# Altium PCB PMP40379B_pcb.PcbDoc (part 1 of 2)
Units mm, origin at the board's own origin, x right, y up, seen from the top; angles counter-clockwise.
Board outline 160 x 130 mm, 2 copper layers (Top Layer, Bottom Layer), stack 1.575 mm thick; 126 components, 53 nets, 295 pads, 84 vias.
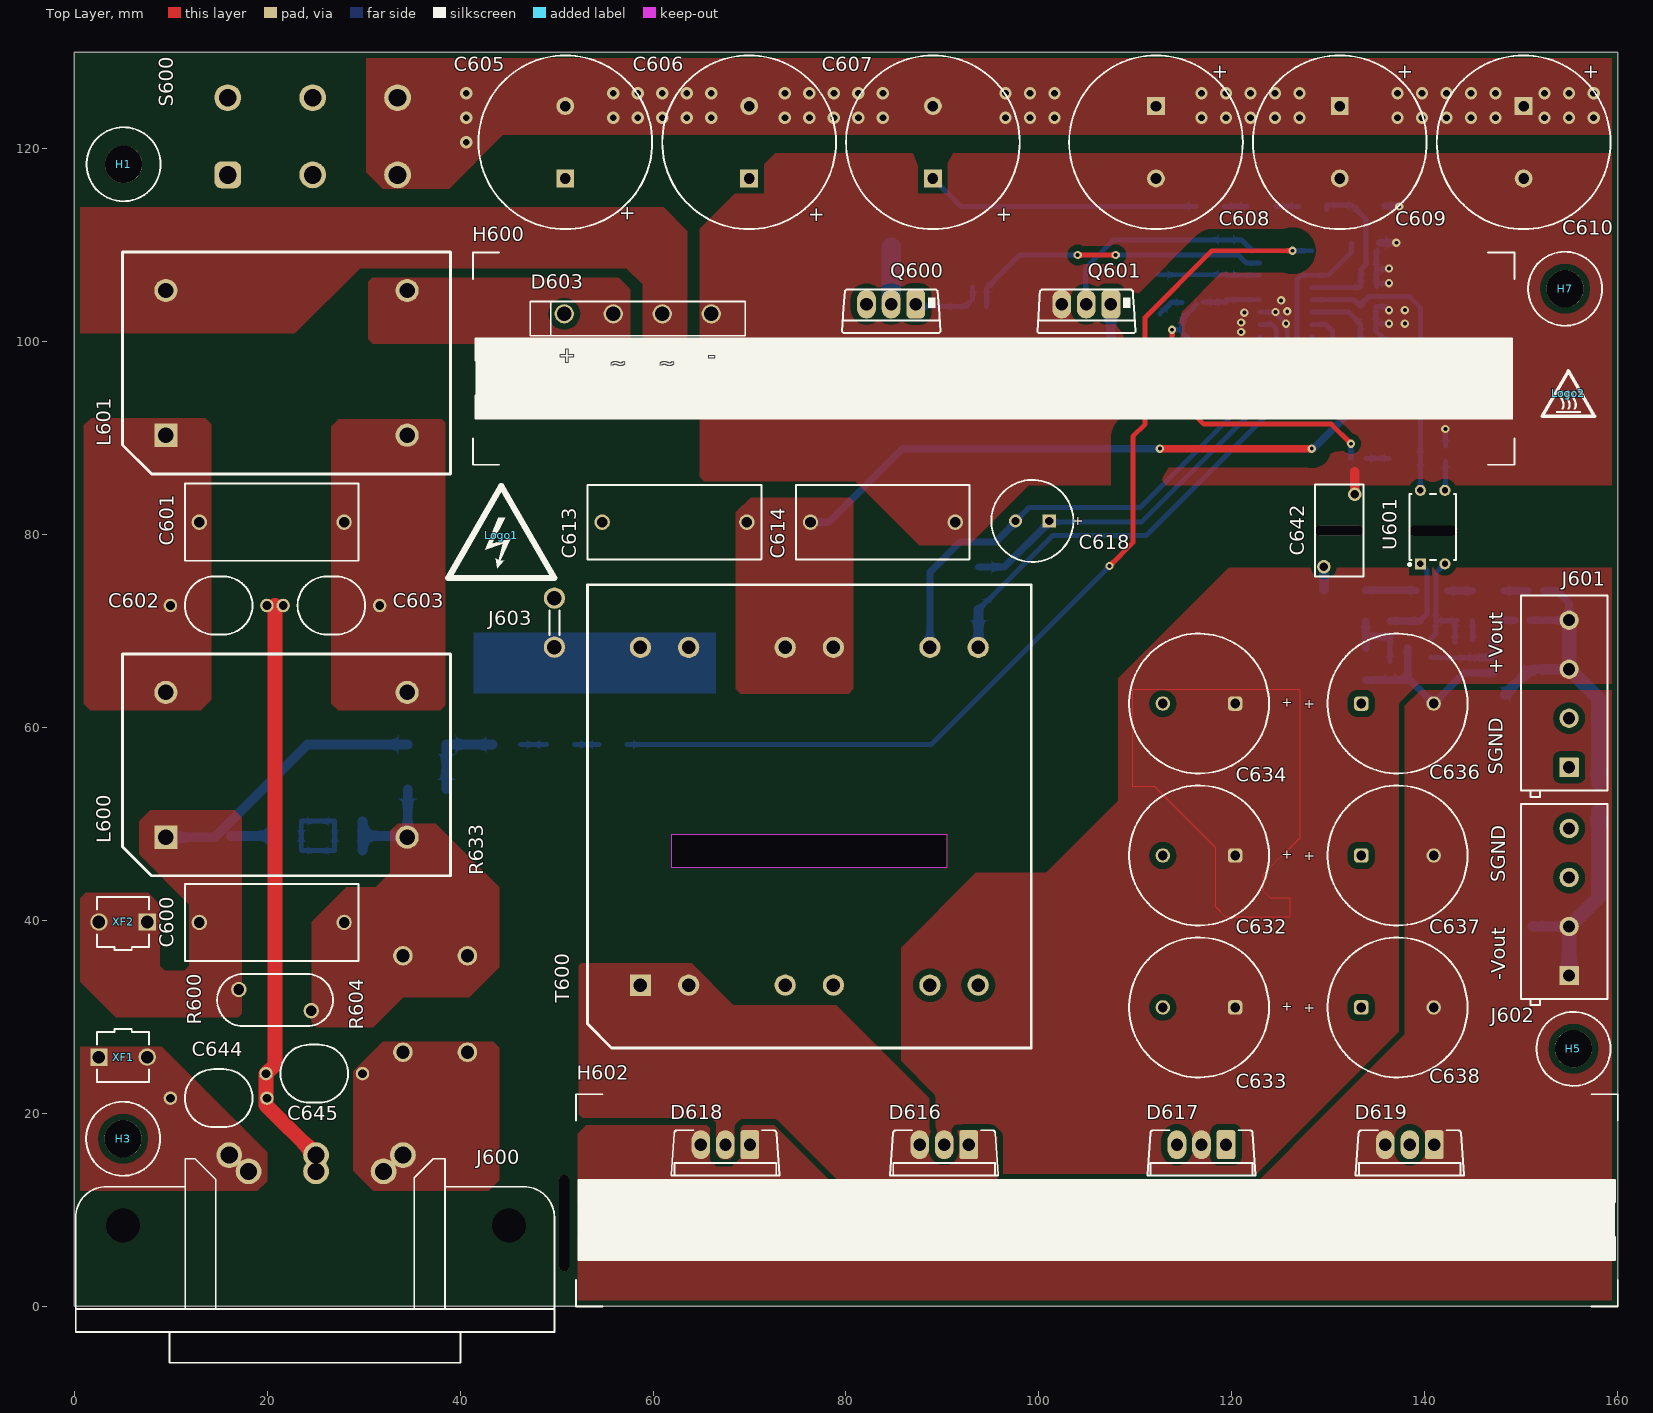
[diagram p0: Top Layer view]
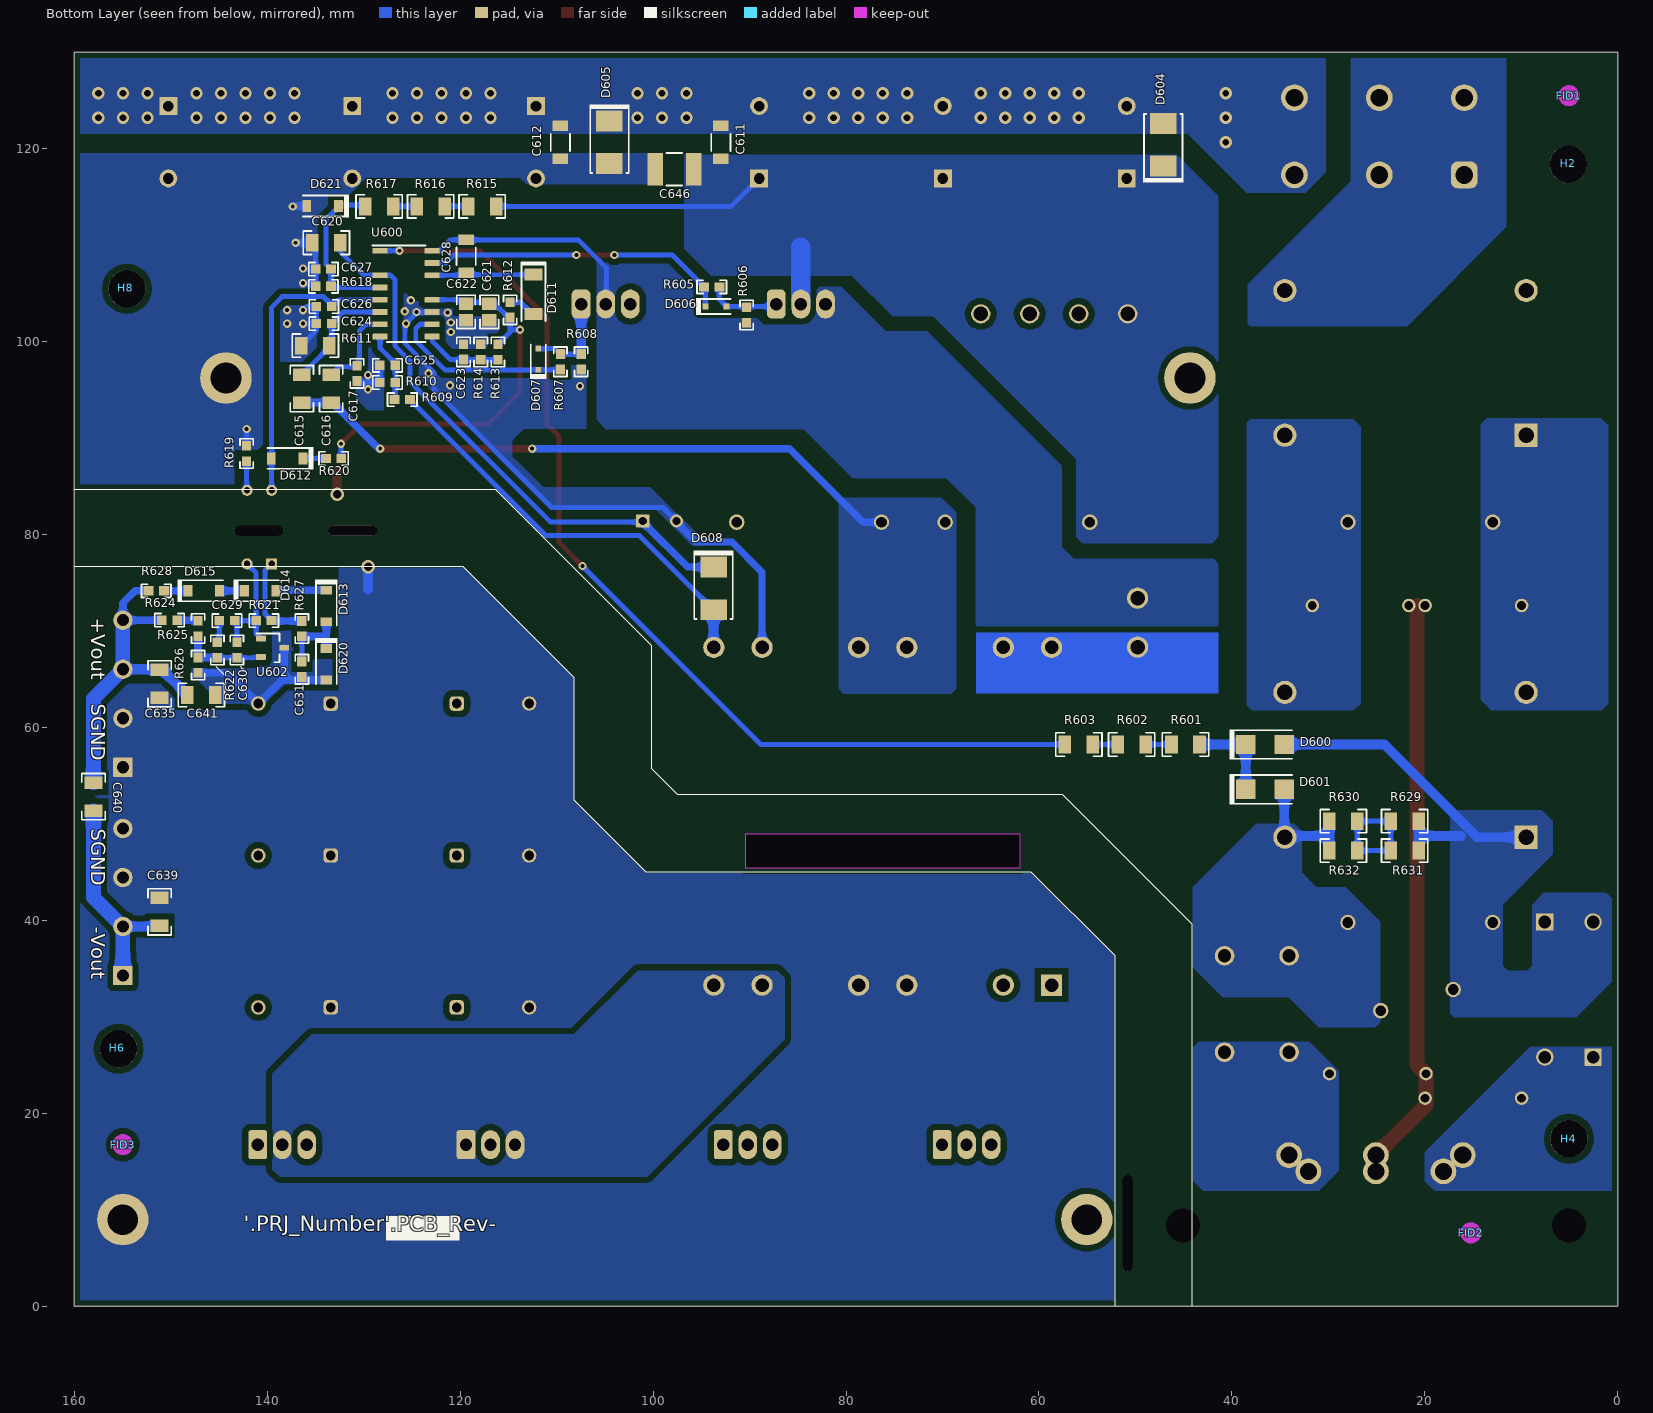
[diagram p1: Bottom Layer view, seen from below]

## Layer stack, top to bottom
Top Solder: solder mask 0.0102, Solder Resist, Dk 3.5
Top Layer: signal copper 0.0356
Dielectric1: core 1.5037, FR-4, Dk 4.8
Bottom Layer: signal copper 0.0356
Bottom Solder: solder mask 0.0102, Solder Resist, Dk 3.5

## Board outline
0,0 0,130 160,130 160,0
cut-out: 61.95,48.95 90.45,48.95 90.45,45.45 61.95,45.45

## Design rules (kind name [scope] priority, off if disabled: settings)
AcuteAngle [All] p1: minimum=4.50000000000000E+0001 checktracksonly=FALSE
AssemblyTestPointUsage [All] p1: valid=2
BoardOutlineClearance BoardOutlineClearance_MountingHoles [OnCopper and InComponentClass('Mounting Holes')] p1: gap=1.016 ignorepadtopadclearanceinfootprint=FALSE
BoardOutlineClearance BoardOutlineClearance_Poly [OnCopper and IsPoly] p2: gap=0.635 ignorepadtopadclearanceinfootprint=FALSE
BoardOutlineClearance [OnCopper and Not InComponentClass('Logo') and not InComponentClass('FiducialMark') and not InRegion(1000,500,4000,800) and not InPoly] p3: gap=1.905 ignorepadtopadclearanceinfootprint=FALSE
Clearance "Schematic Clearance Constraint_2" [InNet('NetC628_1')] p1: gap=2.5 ignorepadtopadclearanceinfootprint=FALSE
Clearance "Schematic Clearance Constraint" [InNet('NetR603_1')] p2: gap=2 ignorepadtopadclearanceinfootprint=FALSE
Clearance "Schematic Clearance Constraint_1" [InNet('NetC613_2')] p3: gap=1.6 ignorepadtopadclearanceinfootprint=FALSE
Clearance Clearance_Keepouts [((IsTrack Or IsArc) And Not InPoly) And IsFree and IsKeepOut vs ((IsTrack Or IsArc) And Not InPoly) And IsFree and IsKeepOut] p4: gap=0 ignorepadtopadclearanceinfootprint=FALSE
Clearance Clearance_Poly [InPolygon] p5: gap=0.635 ignorepadtopadclearanceinfootprint=FALSE except(0: Arc-Hole Track-Hole SMDPad-Hole THPad-Hole Via-Hole Fill-Hole Poly-Hole Region-Hole Text-Hole)
Clearance Clearance_FiducialMark [IsKeepOut and InComponentClass('FiducialMark') vs IsPad and InComponentClass('FiducialMark')] p6: gap=2 ignorepadtopadclearanceinfootprint=FALSE
Clearance [All] p7: gap=0.2 ignorepadtopadclearanceinfootprint=FALSE except(0: Arc-Hole Track-Hole SMDPad-Hole THPad-Hole Via-Hole Fill-Hole Poly-Hole Region-Hole Text-Hole)
ComponentClearance ComponentClearance_MountingHoles_FiducialMarks [InComponentClass('Mounting Holes') vs InComponentClass('FiducialMark')] p1: gap=1.27 collisioncheckmode=3 verticalgap=0.254 showdistances=FALSE
ComponentClearance ComponentClearance_Shunt [InComponentClass('Header') vs InComponentClass('Shunt')] p2: gap=0 collisioncheckmode=3 verticalgap=0 showdistances=FALSE
ComponentClearance ComponentClearance_Logo [InComponentClass('Logo')] p3: gap=1.27 collisioncheckmode=3 verticalgap=0.254 showdistances=FALSE
ComponentClearance ComponentClearance_ScrewToNut [(HasFootprint('NY PMS 440 0025 PH')) vs (HasFootprint('Keystone_1902C'))] p4: gap=0.127 collisioncheckmode=3 verticalgap=0.254 showdistances=FALSE
ComponentClearance ComponentClearance_MountingHoles [InComponentClass('Mounting Holes')] p5: gap=6.35 collisioncheckmode=3 verticalgap=2540 showdistances=FALSE
ComponentClearance ComponentClearance_SmallPassives [HasFootprint('0201*') or HasFootprint('0402*') or HasFootprint('0508') or HasFootprint('0603*') or HasFootprint('0612') or HasFootprint('0805*') or HasFootprint('0815*') or HasFootprint('0830*') or HasFootprint('1206*') or HasFootprint('1210*') or HasFootprint('1808*') or HasFootprint('1812*') or HasFootprint('1825*') or HasFootprint('2010*') or HasFootprint('2220*') or HasFootprint('2225*') or HasFootprint('2512*') or HasFootprint('2728*') or HasFootprint('3518*') vs HasFootprint('0201*') or HasFootprint('0402*') or HasFootprint('0508') or HasFootprint('0603*') or HasFootprint('0612') or HasFootprint('0805*') or HasFootprint('0815*') or HasFootprint('0830*') or HasFootprint('1206*') or HasFootprint('1210*') or HasFootprint('1808*') or HasFootprint('1812*') or HasFootprint('1825*') or HasFootprint('2010*') or HasFootprint('2220*') or HasFootprint('2225*') or HasFootprint('2512*') or HasFootprint('2728*') or HasFootprint('3518*')] p6: gap=0.38 collisioncheckmode=3 verticalgap=0.254 showdistances=FALSE
ComponentClearance ComponentClearance_THtoSMT [IsThruComponent vs IsSMTComponent] p7: gap=1.016 collisioncheckmode=3 verticalgap=0.762 showdistances=FALSE
ComponentClearance ComponentClearance_THtoTH [IsThruComponent vs IsThruComponent] p8: gap=0.762 collisioncheckmode=3 verticalgap=0.762 showdistances=FALSE
ComponentClearance [All] p9: gap=0.762 collisioncheckmode=3 verticalgap=0.254 showdistances=FALSE
DiffPairsRouting [All] p1: maxlimit=2.54 minlimit=0.254 mostfreqgap=0.254 toplayer_minwidth=0.381 toplayer_maxwidth=0.381 toplayer_prefwidth=0.381 bottomlayer_minwidth=0.381 bottomlayer_maxwidth=0.381 bottomlayer_prefwidth=0.381 maxuncoupledlength=25.4
FabricationTestPointUsage TestPointUsage [All] p1: valid=2 allowmultiple=FALSE
FabricationTestpoint Testpoint [All] p1: side=3 testpointundercomponent=TRUE minsize=1.016 maxsize=2.54 preferedsize=1.524 minholesize=0 maxholesize=1.016 preferedholesize=0.813 testpointgrid=0.025 allowsidetop=TRUE allowsidebottom=TRUE usegrid=TRUE gridtolerance=0
FanoutControl Fanout_LCC [IsLCC] p1: bgadir=Out bgaviamode=Centered fanoutstyle=Auto fanoutdirection=Alternating viagrid=0.025 // Fanout_LCC (Default Rule)
FanoutControl Fanout_BGA [IsBGA] p2: bgadir=Out bgaviamode=Centered fanoutstyle=Auto fanoutdirection=Alternating viagrid=0.025 // Fanout_BGA (Default Rule)
FanoutControl Fanout_Default [All] p4: bgadir=Out bgaviamode=Centered fanoutstyle=Auto fanoutdirection=Alternating viagrid=0.025 // Fanout_Default (Default Rule)
FanoutControl Fanout_Small [(CompPinCount < 5)] p5: bgadir=Out bgaviamode=Centered fanoutstyle=Auto fanoutdirection=OutThenIn viagrid=0.025 // Fanout_Small (Default Rule)
HoleSize [All] p1: absolutevalues=TRUE maxlimit=6.375 minlimit=0.2 maxpercent=80.000 minpercent=20.000
MinimumAnnularRing MinimumAnnularRing_ThermalPadVias [IsVia and InAnyComponent] p1: minimumring=0.15
MinimumAnnularRing [All] p2: minimumring=0.203
MinimumSolderMaskSliver MinimumSolderMaskSliver_Logo [InComponentClass('Logo') vs InComponentClass('Logo')] p1: minsoldermaskwidth=0.018
MinimumSolderMaskSliver [All] p2: minsoldermaskwidth=0.1
PlaneConnect [All] p1: planeconnectstyle=Relief reliefexpansion=0.254 reliefentries=4 reliefconductorwidth=0.254 reliefairgap=0.254
PolygonConnect [All] p1: connectstyle=Direct reliefconductorwidth=0.254 reliefentries=4 polygonreliefangle="90 Angle" airgapwidth=0.254
RoutingVias ThermalPadVias [IsVia and InAnyComponent] p1: holewidth=0.2 width=0.5 viastyle="Through Hole" minholewidth=0.2 minwidth=0.5 maxholewidth=0.33 maxwidth=0.6
RoutingVias [All] p2: holewidth=0.406 width=0.864 viastyle="Through Hole" minholewidth=0.2 minwidth=0.66 maxholewidth=1.016 maxwidth=1.651
SilkToBoardRegionClearance [Not ((IsComment or IsDesignator) And (Hide <> 'False')) and not InRegion(1000,500,4000,800)] p1:
SilkToSilkClearance SilkToSilkClearance_Pb-FreeLogo [(HasFootprint('Pb-Free_Overlay_Medium') OR HasFootprint('Pb-Free_Overlay_Small')) vs (HasFootprint('Pb-Free_Overlay_Medium') OR HasFootprint('Pb-Free_Overlay_Small'))] p1: silktosilkclearance=0
SilkToSilkClearance [All] p2: silktosilkclearance=0.102
SilkToSolderMaskClearance SilkToComponentPadClearance [(IsPad or IsFill or IsRegion) and InAnycomponent] p1: minsilkscreentomaskgap=0.127 clearancetoexposedcopper=TRUE
SilkToSolderMaskClearance "Silk to Solder Mask Opening" [All] p2: minsilkscreentomaskgap=0.102 clearancetoexposedcopper=FALSE
SolderMaskExpansion [All] p1: expansion=0.05
Width [All] p1: maxlimit=2.54 minlimit=0.152 preferedwidth=0.254 checkconnectedcopper=TRUE
15 further rules are at their usual default settings.

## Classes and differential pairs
component class FiducialMark: FID1 FID2 FID3
net class HV: NetC613_2 NetC628_1 NetR603_1

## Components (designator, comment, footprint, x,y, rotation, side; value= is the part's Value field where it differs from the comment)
C600 "275V AC, 470 nF" WCAP-FTX2_18x8x14_CS 20.483,39.797 r0 top value="470 nF"
C601 "275V AC, 470 nF" WCAP-FTX2_18x8x14_CS 20.483,81.28 r0 top value="470 nF"
C602 "CD45-E2GA102M-NKA" CD45_700x600x1100 14.986,72.644 r0 top value=1000pF
C603 "CD45-E2GA102M-NKA" CD45_700x600x1100 26.67,72.644 r180 top value=1000pF
C605 "EPAG201ELL561MM45S" CAPPR7.5-18x40 50.91,120.65 r90 top value=560uF
C606 "EPAG201ELL561MM45S" CAPPR7.5-18x40 69.96,120.65 r90 top value=560uF
C607 "EPAG201ELL561MM45S" CAPPR7.5-18x40 89.01,120.65 r90 top value=560uF
C608 "EPAG201ELL561MM45S" CAPPR7.5-18x40 112.124,120.65 r270 top value=560uF
C609 "EPAG201ELL561MM45S" CAPPR7.5-18x40 131.174,120.65 r270 top value=560uF
C610 "EPAG201ELL561MM45S" CAPPR7.5-18x40 150.224,120.65 r270 top value=560uF
C611 "GRM31CR72E104KW03L" 1206_180 92.964,120.65 r90 bottom value=0.1uF
C612 "GRM31CR72E104KW03L" 1206_180 109.601,120.65 r270 bottom value=0.1uF
C613 "ECW-F6104JL" CAPRR1500W80L1800T770H1210 62.23,81.28 r0 top value=0.1uF
C614 "ECW-F6104JL" CAPRR1500W80L1800T770H1210 83.82,81.28 r0 top value=0.1uF
C615 "GRM31A5C2J151JW01D" 1206 136.398,95.123 r90 bottom value=150pF
C616 "GRM31A5C2J151JW01D" 1206 133.35,95.123 r90 bottom value=150pF
C617 "C0603C153J3GACTU" 0603 130.683,96.703 r270 bottom value=0.015uF
C618 "EKZE350ELL271MH20D" Chemi-Con_800x2000 99.314,81.407 r180 top value=270uF
C620 "C3216X7R1V475K085AC" 1206 133.858,110.236 r180 bottom value=4.7uF
C621 "GRM21BC71C106KE11L" 0805 116.967,103.073 r270 bottom value=10uF
C622 "GRM21BC71C106KE11L" 0805 119.38,103.073 r270 bottom value=10uF
C623 "C1608X7R1H104K080AA" 0603 119.634,98.931 r90 bottom value=0.1uF
C624 "GRM1885C1H102JA01D" 0603 134.112,101.854 r180 bottom value=1000pF
C625 "06035A2R2CAT2A" 0603 127.508,97.536 r0 bottom value=2.2pF
C626 "GRM1885C2A102JA01D" 0603 134.112,103.632 r0 bottom value=1000pF
C627 "GRM188R71H221KA01D" 0603 134.168,107.501 r0 bottom value=220pF
C628 "GRM31CR71C475KA01L" 1206_180 119.36,108.839 r90 bottom value=4.7uF
C629 "C0603X471K5RACTU" 0603 144.141,71.073 r180 bottom value=470pF
C630 "06035A100JAT2A" 0603 143.125,68.025 r90 bottom value=10pF
C631 "06033C104JAT2A" 0603 136.398,66.04 r270 bottom value=0.1uF
C632 "EGXF500ELL202MU40S" Chemi-Con_1450x2000 116.586,46.736 r180 top value=2000uF
C633 "EGXF500ELL202MU40S" Chemi-Con_1450x2000 116.586,30.988 r180 top value=2000uF
C634 "EGXF500ELL202MU40S" Chemi-Con_1450x2000 116.586,62.484 r180 top value=2000uF
C635 "12061C104JAT2A" 1206 151.13,64.516 r270 bottom value=0.1uF
C636 "EGXF500ELL202MU40S" Chemi-Con_1450x2000 137.16,62.484 r0 top value=2000uF
C637 "EGXF500ELL202MU40S" Chemi-Con_1450x2000 137.16,46.736 r0 top value=2000uF
C638 "EGXF500ELL202MU40S" Chemi-Con_1450x2000 137.16,30.988 r0 top value=2000uF
C639 "12061C104JAT2A" 1206 151.13,40.894 r270 bottom value=0.1uF
C640 "12061C104JAT2A" 1206 157.988,52.832 r270 bottom value=0.1uF
C641 "12061C104JAT2A" 1206 146.812,63.373 r180 bottom value=0.1uF
C642 "AY2222M35Y5US63L7" AY2_950x500_Straight 131.126,80.412 r90 top value=2200pF
C644 "CD45-E2GA102M-NKA" CD45_700x600x1100 14.986,21.59 r0 top value=1000pF
C645 "CD45-E2GA102M-NKA" CD45_700x600x1100 24.892,24.13 r0 top value=1000pF
C646 "1812Y5000474KXTWS2" 1812_254 97.79,117.856 r0 bottom value=0.47uF
D600 "MURA160T3G" SMA 36.576,58.242 r180 bottom value=1.05V
D601 "MURA160T3G" SMA 36.576,53.594 r180 bottom value=1.05V
D603 "GBU8J-BP" GBU 58.42,102.87 r0 top value=420V
D604 "P6SMB220A-E3/52" SMB 47.117,120.396 r90 bottom value=220V
D605 "P6SMB220A-E3/52" SMB 104.521,120.65 r270 bottom value=220V
D606 "MMDL914-TP" SOD-323 93.472,103.632 r180 bottom value=100V
D607 "MMDL914-TP" SOD-323 111.887,98.171 r90 bottom value=100V
D608 "STPS160UY" SMB 93.726,74.422 r270 bottom value=60V
D611 "ES1JAF" SMAF 112.395,104.902 r270 bottom value=600V
D612 "MMSZ4691T1G" SOD-123 137.922,87.884 r0 bottom value=6.2V
D613 "MMSZ5252B-7-F" SOD-123 133.858,72.593 r270 bottom value=24V
D614 "MMSZ5252B-7-F" SOD-123 140.716,74.168 r180 bottom value=24V
D615 "MMSZ5252B-7-F" SOD-123 146.558,74.168 r180 bottom value=24V
D616 "STPS41H100CTY" TO-220AB 90.17,16.764 r180 top value=100V
D617 "STPS41H100CTY" TO-220AB 116.84,16.764 r180 top value=100V
D618 "STPS41H100CTY" TO-220AB 67.5,16.764 r180 top value=100V
D619 "STPS41H100CTY" TO-220AB 138.43,16.764 r180 top value=100V
D620 "MMSZ5242B-7-F" SOD-123 133.858,66.548 r270 bottom value=12V
D621 "MMSZ5227B-7-F" SOD-123 134.239,114.046 r0 bottom value=3.6V
FID1 "Fiducial" Fiducial10-20 5.08,125.476 r180 bottom
FID2 "Fiducial" Fiducial10-20 15.24,7.62 r180 bottom
FID3 "Fiducial" Fiducial10-20 154.94,16.764 r180 bottom
H1 "4824" KEYSTONE_4824 5.13,118.372 r0 top
H2 "1903C" KEYSTONE_1903C 5.13,118.493 r180 bottom
H3 "4824" KEYSTONE_4824 5.08,17.382 r0 top
H4 "1903C" KEYSTONE_1903C 5.08,17.382 r90 bottom
H5 "4824" KEYSTONE_4824 155.392,26.702 r0 top
H6 "1903C" KEYSTONE_1903C 155.512,26.821 r90 bottom
H7 "4824" KEYSTONE_4824 154.52,105.473 r0 top
H8 "1903C" KEYSTONE_1903C 154.64,105.592 r90 bottom
H600 "782653B04250G" HEATSINK_782653B04250G 95.31,98.22 r0 top locked
H602 "782653B04250G" HEATSINK_782653B04250G 106,11 r0 top locked
J600 "703W-00/54" CONN_QUALTEK-703W-0054 25.08,5.655 r180 top
J601 "ED120/4DS" On-Shore_ED120_4DS 154.94,63.5 r90 top
J602 "ED120/4DS" On-Shore_ED120_4DS 154.94,41.91 r90 top
J603 "1430-1" Keystone_1430-1 49.784,70.866 r270 top
L600 "7448051012" "WE-CMBNC_Type XL_7448051012" 22.015,56.134 r0 top value=12mH
L601 "7448051012" "WE-CMBNC_Type XL_7448051012" 22.015,97.79 r0 top value=12mH
Logo1 "DANGER HIGH VOLTAGE" IEC_HighVoltage_Medium 44.272,79.934 r0 top
Logo2 "CAUTION HOT SURFACE" IEC_HotSurface_Small 154.864,94.615 r0 top
Q600 "IPA65R190CFD" TO-220FP 84.676,103.886 r180 top value=650V
Q601 "IPA65R190CFD" TO-220FP 104.902,103.886 r180 top value=650V
R600 "S10K275E2" VAR_S10K275E2 20.828,31.75 r0 top value=275V
R601 "CRCW12061K65FKEA" 1206 44.817,58.24 r180 bottom value=1.65k
R602 "CRCW12061K65FKEA" 1206 50.405,58.24 r180 bottom value=1.65k
R603 "CRCW12061K65FKEA" 1206 55.866,58.24 r180 bottom value=1.65k
R604 "B57364S0100M051" SPNL20 34.083,31.347 r270 top value=10
R605 "CRCW060310R0FKEA" 0603 93.917,105.664 r180 bottom value=10.0
R606 "RC0603JR-0710KL" 0603 90.297,102.743 r90 bottom value=10k
R607 "CRCW060310R0FKEA" 0603 109.601,97.902 r90 bottom value=10.0
R608 "RC0603JR-0710KL" 0603 107.442,97.902 r90 bottom value=10k
R609 "CRCW060336K5FKEA" 0603 125.984,93.98 r180 bottom value=36.5k
R610 "CRCW060310K0FKEA" 0603 127.508,95.758 r180 bottom value=10.0k
R611 "RC1206FR-07150RL" 1206 135.001,99.568 r180 bottom value=150
R612 "CRCW06032R20JNEA" 0603 114.808,103.286 r90 bottom value=2.2
R613 "CRCW0603787KFKEA" 0603 116.078,98.918 r90 bottom value=787k
R614 "CRCW0603300KJNEA" 0603 117.856,98.918 r270 bottom value=300k
R615 "CRCW12064M99FKEA" 1206 117.711,114.012 r180 bottom value=4.99Meg
R616 "CRCW12064M99FKEA" 1206 123.045,114.012 r180 bottom value=4.99Meg
R617 "CRCW12064M99FKEA" 1206 128.379,114.012 r180 bottom value=4.99Meg
R618 "RC0603FR-07169KL" 0603 134.168,105.723 r180 bottom value=169k
R619 "CRCW06030000Z0EA" 0603 142.113,88.392 r270 bottom value=0
R620 "CRCW060310K0JNEA" 0603 133.096,87.884 r180 bottom value=10k
R621 "CRCW06036K04FKEA" 0603 140.331,71.073 r180 bottom value=6.04k
R622 "CRCW0603806KFKEA" 0603 145.157,68.025 r270 bottom value=806k
R624 "CRCW060351R0JNEA" 0603 150.114,71.12 r0 bottom value=51
R625 "CRCW0603255KFKEA" 0603 147.146,70.269 r90 bottom value=255k
R626 "CRCW06037K50JNEA" 0603 147.146,66.459 r90 bottom value=7.5k
R627 "CRCW060327K0JNEA" 0603 136.398,70.242 r270 bottom value=27k
R628 "CRCW0603100RJNEA" 0603 151.486,74.168 r180 bottom value=100
R629 "CRCW12061M00JNEA" 1206 22.098,50.292 r180 bottom value=1.0Meg
R630 "CRCW12061M00JNEA" 1206 28.448,50.292 r180 bottom value=1.0Meg
R631 "CRCW12061M00JNEA" 1206 22.098,47.244 r180 bottom value=1.0Meg
R632 "CRCW12061M00JNEA" 1206 28.448,47.244 r180 bottom value=1.0Meg
R633 "B57364S0100M051" SPNL20 40.767,31.347 r270 top value=10
S600 "V80212MS02Q" SW_V80212MS02Q 24.73,121.27 r90 top
T600 "TBD" WE-LLCR_ETD44 76.2,50.8 r90 top locked value=25uH
U600 "UCC25630-2DDBR" DDB0014A 125.582,104.961 r180 bottom
U601 "VO618A" DIP-4 140.796,80.772 r90 top
U602 "TL431AIDBZR" DBZ0003A_N 139.422,68.26 r180 bottom
XF1 "0751.0052" SCHURTER_0751_0052 5.08,25.846 r90 top
XF2 "0751.0052" SCHURTER_0751_0052 5.08,39.846 r270 top

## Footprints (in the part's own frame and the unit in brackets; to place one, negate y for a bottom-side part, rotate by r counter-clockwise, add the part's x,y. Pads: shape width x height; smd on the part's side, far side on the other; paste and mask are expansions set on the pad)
0603 [mm] "0603 from SM-752 data"
  rect 1x0.95 smd: 1(-0.8,0) 2(0.8,0)
  silkscreen extent -1.52,-0.69 1.52,0.69, body extent -0.87,-0.47 0.87,0.47, height 1
0805 [mm] "0805 from SM-752 data"
  rect 1.3x1.5 smd: 1(-0.85,0) 2(0.85,0)
  silkscreen extent -1.72,-0.97 1.72,0.97, body extent -1.1,-0.72 1.1,0.72, height 1.45
1206 [mm] "1206 from SM-752 data"
  rect 1.3x1.85 smd: 1(-1.45,0) 2(1.45,0)
  silkscreen extent -2.4,-1.21 2.4,1.21, body extent -1.7,-0.9 1.7,0.9, height 1.35
1206_180 [mm] "1206_180"
  rect 1.1x1.6 smd: 1(-1.7,0) 2(1.7,0)
  silkscreen extent -0.9,-1 0.9,1, body extent -1.75,-0.95 1.75,0.95, height 1.8
1812_254 [mm] "SMD, 2-Leads, Body 4.8x3.4mm"
  rect 1.6x3.4 smd: 1(-2,0) 2(2,0)
  silkscreen extent -0.8,-1.7 0.8,1.7, body extent -2.4,-1.7 2.4,1.7, height 2.54
AY2_950x500_Straight [mm] "TH, 2-Leads, 9.5x5mm, Pin Spacing 7.5mm"
  round 1.4 hole 0.9: 1(-3.75,1.6) 2(3.75,-1.6)
  silkscreen extent -4.75,-2.5 4.75,2.5, body extent -4.74,-2.5 4.75,2.5, height 12.5
CAPPR7.5-18x40 [mm] "Capacitor, Electrolytic, Radial; Body 18 x 40 mm (Dia.xH typ); Pin Spacing 7.5 mm (typ)"
  rect 1.85x1.85 hole 1.1: 1(-3.75,0)
  round 1.85 hole 1.1: 2(3.75,0)
  silkscreen extent -9,-9 9,9, body extent -9,-9.01 9,9.01, height 42
CAPRR1500W80L1800T770H1210 [mm] "PANASONIC"
  round 1.6 hole 1.1: 1(-7.5,0) 2(7.5,0)
  silkscreen extent -9,-3.85 9,3.85, body extent -9,-3.85 9,3.85, height 13.6
CD45_700x600x1100 [mm] "TH, 2-Leads, Dia 7mm, Pin Spacing 10 mm"
  round 1.4 hole 0.9: 1(-5,0) 2(5,0)
  silkscreen extent -3.5,-3 3.5,3, body extent -5.34,-3.02 5.34,3.02, height 11
Chemi-Con_800x2000 [mm] "TH, 2-Leads, Dia 8mm, Pin Spacing 3.5mm"
  rect 1.35x1.35 hole 0.85: 1(-1.75,0)
  round 1.35 hole 0.85: 2(1.75,0)
  silkscreen extent -4.25,-4.25 4.25,4.25, body extent -4.25,-4.25 4.26,4.25, height 21.51
Chemi-Con_1450x2000 [mm] "TH, 2-Leads, Dia 14.5mm"
  rrect50% 1.5x1.5 hole 1: 1(-3.75,0)
  round 1.5 hole 1: 2(3.75,0)
  silkscreen extent -7.25,-7.25 7.25,7.25, body extent -7.25,-7.25 7.26,7.25, height 21.51
CONN_QUALTEK-703W-0054 [mil] "AC Receptacle"
  round 105 hole 70: 1(354.33,-395) 2(-354.33,-395) 3(0,-395)
  round 39.37 hole 137.8 unplated: MH1(-787.4,-107.36) MH2(787.4,-107.36)
  silkscreen extent -972,-380 981,452, body extent -972,-477 981,452, height 1130
DBZ0003A_N [mm] "SOT23, 3-Leads, Body 2.9x1.3mm, Pitch 0.95mm, Lead Span 2.4mm, IPC Medium Density"
  rrect17% 1x0.6 smd: 1(-1.2,0.95) 2(-1.2,-0.95) 3(1.2,0)
  silkscreen extent -1.65,-1.5 0.7,1.5, body extent -1.26,-1.46 1.26,1.46, height 0.98
DDB0014A [mm] "SMD, 14-Leads, Body 3.9x9.9mm, Pitch 1.27mm"
  rrect17% 1.55x0.6 smd: 1(-2.7,4.445) 3(-2.7,1.905) 4(-2.7,0.635) 5(-2.7,-0.635) 6(-2.7,-1.905) 7(-2.7,-3.175) 8(-2.7,-4.445) 9(2.7,-4.445) 10(2.7,-3.175) 11(2.7,-1.905) 12(2.7,-0.635) 14(2.7,1.905) 15(2.7,3.175) 16(2.7,4.445)
  silkscreen extent -3.5,-5 2,5, body extent -3.01,-4.95 3.01,4.95, height 1.75
DIP-4 [mm] "DIP, 4-Leads, Body 6.86x4.83mm, Pitch 2.54mm"
  rect 1.15x1.15 hole 0.65: 1(-3.81,1.27)
  round 1.15 hole 0.65: 2(-3.81,-1.27) 3(3.81,-1.27) 4(3.81,1.27)
  silkscreen extent -4,-2.41 3.43,2.52, body extent -4.02,-2.41 4.02,2.41, height 5.59
Fiducial10-20 [mm]
  round 1 smd mask+0.5: 1(0,0)
  Top Layer keep-out circle w1.178: c0,0 r0.5
GBU [mm] "Comchip / Diodes Inc diode bridge"
  round 2 hole 1.5: 1(-7.62,0) 2(-2.54,0) 3(2.54,0) 4(7.62,0)
  silkscreen extent -11.15,-2.28 11.15,1.28, body extent -11.15,-2.28 11.15,1.28, height 21.55
HEATSINK_782653B04250G [mil] "Aavid"
  round 210 hole 125: 1(-2006.1,-78.66) 2(1926.97,-78.66)
  silkscreen extent -2125,-433 2125,433, body extent -2125,-430 2120,420, height 1122
IEC_HighVoltage_Medium [mm]
  silkscreen extent -5.51,-4.46 5.51,5.09
IEC_HotSurface_Small [mm]
  silkscreen extent -2.72,-2.36 2.72,2.35
Keystone_1430-1 [mm] "Pin Shorting, Pin Spacing 5.08mm,  TH"
  round 2.2 hole 1.5: 1(-2.54,0) 2(2.54,0)
  silkscreen extent -1.27,-0.51 1.27,0.51, body extent -3.05,-0.51 3.05,0.51, height 4.63
KEYSTONE_1903C [mil] "HEX NYLON STANDOFF 6-32, F-F 0.5\""
  round 1 on Mech4: 0(0,0)
  body extent -144,-125 144,125, height 501
KEYSTONE_4824 [mil] "HEX STANDOFF 6-32 NYLON 1-1/2\""
  round 1 on Mech3: 0(0,0)
  round 152 hole 152 unplated: MH(0,0)
  silkscreen extent -151,-151 151,151, body extent -144,-125 144,125, height 1500
On-Shore_ED120_4DS [mm] "ONSHORE"
  rrect5% 2x2 hole 1.25: 1(-7.62,0)
  round 2 hole 1.25: 2(-2.54,0) 3(2.54,0) 4(7.62,0)
  silkscreen extent -10.68,-4 10.16,5, body extent -10.86,-4 10.16,5, height 13
SCHURTER_0751_0052 [mm] "TH, 4-Leads, Body 20.2x6mm"
  rect 1.8x1.8 hole 1.3: 1(0,2.5)
  round 1.8 hole 1.3: 2(0,-2.5)
  silkscreen extent -2.6,-2.7 2.9,2.7, body extent -3.5,-3 2.9,3, height 12.3
SMA [mm] "Molded Diode, 2-Leads, Body 4.3x2.6mm, IPC Medium Density, based on OnSemi component dimensions and land pattern"
  rect 2x2 smd: 1(-2,0) 2(2,0)
  silkscreen extent -3.66,-1.57 2.79,1.57, body extent -2.6,-1.3 2.6,1.3, height 2.42
SMAF [mm] "SMD, 2-Leads, Body 3.8x2.5mm"
  rect 1.24x1.89 smd: 1(-2.04,0) 2(2.04,0)
  silkscreen extent -3.4,-1.3 2.8,1.3, body extent -2.35,-1.25 2.35,1.25, height 1
SMB [mm] "Molded Diode, 2-Leads, Body 5.4x3.6mm, IPC Medium Density, based on OnSemi component dimensions"
  rect 2.159x2.743 smd: 1(-2.21,0) 2(2.21,0)
  silkscreen extent -3.94,-2.08 3.17,2.08, body extent -2.7,-1.8 2.7,1.8, height 2.32
SOD-123 [mm] "On Semi recommended land pattern"
  rect 0.915x1.22 smd: 1(-1.637,0) 2(1.637,0)
  silkscreen extent -2.74,-1.17 2.03,1.17, body extent -1.93,-0.9 1.93,0.9, height 1.35
SOD-323 [mm] "NXP recommended land pattern"
  rect 0.6x0.6 smd paste-0.05: 1(-1.1,0) 2(1.1,0)
  silkscreen extent -2.06,-0.86 1.53,0.86, body extent -1.3,-0.67 1.3,0.68, height 1.1
SPNL20 [mm] "TH, 2-Leads, Body 25x6mm, Pin Spacing 10mm"
  round 2.025 hole 1.35: 1(-5,0) 2(5,0)
  body extent -12.5,-3 12.5,3, height 31.5
SW_V80212MS02Q [mm] "TH, 6-Leads, Body 26.19x16.5mm, Pitch 8.8mm"
  rrect50% 2.775x2.775 hole 1.85: 1(-4,8.8)
  round 2.775 hole 1.85: 2(-4,0) 3(-4,-8.8) 4(4,8.8) 5(4,0) 6(4,-8.8)
  body extent -8.25,-13.09 8.26,13.09, height 15.75
TO-220AB [mm] "Copied from Altium's version of TO3B"
  rrect25% 1.93x3 hole 1.27: 1(-2.54,0)
  oval 1.93x3 hole 1.27: 2(0,0) 3(2.54,0)
  silkscreen extent -5.61,-1.49 5.61,3.2, body extent -5.61,-1.49 5.61,3.2, height 19.42
TO-220FP [mm] "FM, Body 10.4x4.6mm, Pitch 2.55mm"
  rrect50% 1.95x3 hole 1.3: 1(-2.55,0)
  oval 1.95x3 hole 1.3: 2(0,0) 3(2.55,0)
  silkscreen extent -5.1,-1.5 5.08,3, body extent -5.09,-1.5 5.09,3, height 19.41
VAR_S10K275E2 [mm] "EPCOS"
  round 1.6 hole 1.1: 1(-3.75,1.1) 2(3.75,-1.1)
  silkscreen extent -6,-2.7 6,2.7, body extent -5.98,-2.7 5.98,2.7, height 14.99
WCAP-FTX2_18x8x14_CS [mm] "Film Capacitors, 18x8x14mm"
  round 1.6 hole 1.1: 1(-7.5,0) 2(7.5,0)
  silkscreen extent -9,-4 9,4, body extent -9,-4 9,4, height 14.05
"WE-CMBNC_Type XL_7448051012" [mm] "THT Common Mode Power Line Choke, 4 leads"
  rect 2.4x2.4 hole 1.6: 1(-12.5,-7.5)
  round 2.4 hole 1.6: 2(12.5,-7.5) 3(12.5,7.5) 4(-12.5,7.5)
  silkscreen extent -17,-11.5 17,11.5, body extent -15.34,-10.3 15.33,10.3, height 30.75
WE-LLCR_ETD44 [mm] "Resonant Converter, body 48x46"
  rect 2.2x2.2 hole 1.4: 1(-17.5,17.5)
  round 2.2 hole 1.4: 2(-17.5,12.5) 4(-17.5,2.5) 5(-17.5,-2.5) 7(-17.5,-12.5) 8(-17.5,-17.5) 9(17.5,-17.5) 10(17.5,-12.5) 12(17.5,-2.5) 13(17.5,2.5) 15(17.5,12.5) 16(17.5,17.5)
  Keep-Out Layer board cut-out: -5.35,14.25 -1.85,14.25 -1.85,-14.25 -5.35,-14.25
  silkscreen extent -24,-23 24,23, body extent -23.3,-22 23.3,22, height 26.85

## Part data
C600 C601: library part 890324025039CS, "WCAP-FTX2 Film Capacitors, 18x8x14mm, 275V AC, 470 nF", Manufacturer="Wurth Electronics", Operating Temperature="-40 °C to +105 °C", Rated Voltage="275V AC"
C602 C603 C644 C645: "CAP, CERM, 1000 pF, X1 440 VAC/Y1 400 VAC, +/- 20%, E, D7xT6mm", Cap_Case=7x6x11mm, Manufacturer=TDK, Supplier Part Number 1=445-174535-ND, TempCo=E, Tolerance_%=20, ValueDisplayed=1000pF
C605 C606 C607 C608 C609 C610: library part Capacitor_Polarized, "CAP ALUM 560UF 20% 200V RADIAL", Lifetime @ Temp.="2000 Hrs @ 105°C", Manufacturer="United Chemi-Con", Operating Temperature="-40°C ~ 105°C", Ratings=-, Supplier Part Number 1=EPAG201ELL561MM45S-ND, Tolerance_%=±20%, Value2=200V
C611 C612: "CAP, CERM, 0.1 µF, 250 V,+/- 10%, X7R, 1206", Cap_Case=1206, Manufacturer=MuRata, Supplier Part Number 1=490-3542-1-ND, TempCo=X7R, Tolerance_%=10, Value2=250V, ValueDisplayed=0.1µF
C613 C614: "CAP, Film, 0.1 µF, 630 V,+/- 5%, TH", Cap_Case="Radial 18x7.7x13.6", Manufacturer=Panasonic, Supplier Part Number 1=P12158-ND, Tolerance_%=5, Value2=630V, ValueDisplayed=0.1µF
C615 C616: "CAP, CERM, 150 pF, 630 V,+/- 5%, C0G/NP0, 1206", Cap_Case=1206, Manufacturer=MuRata, Supplier Part Number 1=490-5274-1-ND, TempCo=C0G/NP0, Tolerance_%=5, Value2=630V, ValueDisplayed=150pF
C617: "CAP, CERM, 0.015 µF, 25 V,+/- 5%, C0G/NP0, 0603", Cap_Case=0603, Manufacturer=Kemet, Supplier Part Number 1=399-10044-1-ND, TempCo=C0G/NP0, Tolerance_%=5, Value2=25V, ValueDisplayed=0.015µF
C618: "CAP, AL, 270 µF, 35 V, +/- 20%, TH", Cap_Case=8x20, Manufacturer=Chemi-Con, Supplier Part Number 1=565-1692-ND, Tolerance_%=20, Value2=35V, ValueDisplayed=270µF
C620: "CAP, CERM, 4.7 µF, 35 V,+/- 10%, X7R, 1206", Cap_Case=1206, Manufacturer=TDK, Supplier Part Number 1=445-14805-1-ND, TempCo=X7R, Tolerance_%=10, Value1="0.003785 ohm", Value2=35V, ValueDisplayed=4.7µF
C621 C622: "CAP, CERM, 10 µF, 16 V,+/- 10%, X7S, 0805", Cap_Case=0805, Manufacturer=MuRata, Supplier Part Number 1=490-12756-1-ND, TempCo=X7S, Tolerance_%=10, Value2=16V, ValueDisplayed=10µF
C623: "CAP, CERM, 0.1 µF, 50 V,+/- 10%, X7R, 0603", Cap_Case=0603, Manufacturer=TDK, Supplier Part Number 1=445-1314-1-ND, TempCo=X7R, Tolerance_%=10, Value1="0.0296 ohm", Value2=50V, ValueDisplayed=0.1µF
C624: "CAP, CERM, 1000 pF, 50 V,+/- 5%, C0G/NP0, 0603", Cap_Case=0603, Manufacturer=MuRata, Supplier Part Number 1=490-1451-1-ND, TempCo=C0G/NP0, Tolerance_%=5, Value2=50V, ValueDisplayed=1000pF
C625: "CAP, CERM, 2.2 pF, 50 V, +/- 11%, C0G/NP0, 0603", Cap_Case=0603, Manufacturer=AVX, Supplier Part Number 1=478-1155-1-ND, TempCo=C0G/NP0, Tolerance_%=11, Value1="1.033 ohm", Value2=50V, ValueDisplayed=2.2pF
C626: "CAP, CERM, 1000 pF, 100 V,+/- 5%, C0G/NP0, 0603", Cap_Case=0603, Manufacturer=MuRata, Supplier Part Number 1=490-3281-1-ND, TempCo=C0G/NP0, Tolerance_%=5, Value2=100V, ValueDisplayed=1000pF
C627: "CAP, CERM, 220 pF, 50 V, +/- 10%, X7R, 0603", Cap_Case=0603, Manufacturer=MuRata, Supplier Part Number 1=490-1483-1-ND, TempCo=X7R, Tolerance_%=10, Value1=Unknown, Value2=50V, ValueDisplayed=220pF
C628: "CAP, CERM, 4.7 µF, 16 V,+/- 10%, X7R, 1206", Cap_Case=1206, Manufacturer=MuRata, Supplier Part Number 1=490-3370-1-ND, TempCo=X7R, Tolerance_%=10, Value2=16V, ValueDisplayed=4.7µF
C629: "CAP, CERM, 470 pF, 50 V, +/- 10%, X7R, 0603", Cap_Case=0603, Manufacturer=Kemet, Supplier Part Number 1=399-5338-1-ND, TempCo=X7R, Tolerance_%=10, Value1=Unknown, Value2=50V, ValueDisplayed=470pF
C630: "CAP, CERM, 10 pF, 50 V, +/- 5%, C0G/NP0, 0603", Cap_Case=0603, Manufacturer=AVX, Supplier Part Number 1=478-1163-1-ND, TempCo=C0G/NP0, Tolerance_%=5, Value1="0.403 ohm", Value2=50V, ValueDisplayed=10pF
C631: "CAP, CERM, 0.1 µF, 25 V, +/- 5%, X7R, 0603", Cap_Case=0603, Manufacturer=AVX, Supplier Part Number 1=478-3713-1-ND, TempCo=X7R, Tolerance_%=5, Value1="0.05 ohm", Value2=25V, ValueDisplayed=0.1µF
C632 C633 C634 C636 C637 C638: library part Capacitor_Polarized, "CAP ALUM 2000UF 20% 50V RADIAL", Lifetime @ Temp.="3000 Hrs @ 125°C", Manufacturer="United Chemi-Con", Operating Temperature="-40°C ~ 125°C", Ratings=AEC-Q200, Supplier Part Number 1=EGXF500ELL202MU40S-ND, Tolerance_%=±20%, Value2=50V
C635 C639 C640 C641: "CAP, CERM, 0.1 µF, 100 V,+/- 5%, X7R, 1206", Cap_Case=1206, Manufacturer=AVX, Supplier Part Number 1=478-3785-1-ND, TempCo=X7R, Tolerance_%=5, Value1="0.037 ohm", Value2=100V, ValueDisplayed=0.1µF
C642: "CAP, CERM, 2200 pF, 300 V, +/- 20%, Y5U, AEC-Q200 Grade 1, D9.5xT5mm", Cap_Case=9.5x5mm, Manufacturer=Vishay-Bccomponents, Supplier Part Number 1=BC2914-ND, TempCo=Y5U, Tolerance_%=20, Value1=Unknown, Value2=300V, ValueDisplayed=2200pF
C646: "CAP, CERM, 0.47 µF, 500 V,+/- 10%, X7R, 1812", Cap_Case=1812, Manufacturer="Knowles Capacitors", Supplier Part Number 1=1608-1155-1-ND, TempCo=X7R, Tolerance_%=10, Value2=500V, ValueDisplayed=0.47µF
D600 D601: "Diode, Ultrafast, 600V, 1A, SMA", Manufacturer="ON Semiconductor", Supplier Part Number 1=MURA160T3GOSCT-ND, Value1=1A, Value2=600V
D603: "Diode, Switching-Bridge, 420 V, 8 A, TH", Manufacturer="Micro Commercial Components", Supplier Part Number 1=GBU8J-BPMS-ND, Value1=8A, Value2=1V
D604 D605: library part Zener, "TVS Diodes - Transient Voltage Suppressors 600W 220V Unidirect", Breakdown Voltage=209V, Case/Package=SMB, Clamping Voltage=328V, Leakage Current=1uA, Manufacturer="Vishay Semiconductors", Max Breakdown Voltage=231V, Max Operating Temperature=150°C, Max Power Dissipation=600W, Max Surge Current=100A, Min Operating Temperature=-65°C, Operating Supply Voltage=185V, Package Quantity=750, Peak Pulse Current=1.8A, Supplier Part Number 1=P6SMB220A-E3/52-ND, Test Current=1mA
D606 D607: "Diode, Switching, 100 V, 0.2 A, SOD-323", Manufacturer="Micro Commercial Components", Supplier Part Number 1=MMDL914-TPMSCT-ND, Value1=0.2A, Value2=1V
D608: "Diode, Schottky, 60 V, 1 A, AEC-Q101, SMB", Manufacturer=STMicroelectronics, Supplier Part Number 1=497-13277-1-ND, Value1=1A, Value2=0.67V
D611: "Diode, Ultrafast, 600 V, 1 A, AEC-Q101, SMAF", Manufacturer="Fairchild Semiconductor", Supplier Part Number 1=ES1JAFCT-ND, Value1=1A, Value2=1.7V
D612: "Diode, Zener, 6.2 V, 500 mW, SOD-123", Manufacturer="ON Semiconductor", Power_W=0.5, Supplier Part Number 1=MMSZ4691T1GOSCT-ND, Value1=0.5W
D613 D614 D615: "Diode, Zener, 24 V, 500 mW, SOD-123", Manufacturer="Diodes Inc.", Power_W=0.5, Supplier Part Number 1=MMSZ5252B-FDICT-ND, Value1=0.5W
D616 D617 D618 D619: "Diode, Schottky, 100 V, 20 A, AEC-Q101, TH", Manufacturer=STMicroelectronics, Supplier Part Number 1=497-15565-5-ND, Value1=20A, Value2=0.8V
D620: "Diode, Zener, 12 V, 500 mW, SOD-123", Manufacturer="Diodes Inc.", Power_W=0.5, Supplier Part Number 1=MMSZ5242B-FDICT-ND, Value1=0.5W
D621: "Diode, Zener, 3.6 V, 500 mW, SOD-123", Manufacturer="Diodes Inc.", Power_W=0.5, Supplier Part Number 1=MMSZ5227B-FDICT-ND, Value1=0.5W
FID1 FID2 FID3: "Fiducial mark.  There is nothing to buy or mount.", Manufacturer=N/A
H1 H3 H5 H7: "HEX STANDOFF 6-32 NYLON 1-1/2\"", Manufacturer=Keystone, Supplier Part Number 1=36-4824-ND
H2 H4 H6 H8: "Standoff, Hex, 0.5\"L #6-32 Nylon", Manufacturer=Keystone, Supplier Part Number 1=36-1903C-ND
H600 H602: library part 782653B02000G, "HEATSINK VERT MAX CLIP, BLACK, 4.25 INCHES", Manufacturer=Aavid
J600: "AC Receptacle, 10A 250VAC", Manufacturer="Qualtek Electronics Corporation", Supplier Part Number 1=Q220-ND
J601 J602: "Terminal Block, 5.08 mm, 4x1, Brass, TH", Color=Blue, Current_A=15, Manufacturer="On-Shore Technology", Supplier Part Number 1=ED2227-ND, Voltage_V=300
J603: "Pin Shorting, Pin Spacing 5.08mm,  TH", Manufacturer=Keystone, Supplier Part Number 1=36-1430-1-ND
L600 L601: library part 744825320, "CMC 12MH 10A 2LN TH", Manufacturer="WURTH ELEKTRONIK", Supplier Part Number 1=75X1231, ValueDisplayed=20mH
Logo1: library part IEC_HighVoltage, "IEC 61010-1 High Voltage Warning"
Logo2: library part IEC_HotSurface, "IEC 61010-1 Hot Surface Warning"
Q600 Q601: "MOSFET, N-CH, 650 V, 17.5 A, TO-220FP", Alternate Manufacturer=None, Manufacturer="Infineon Technologies", Supplier Part Number 1=IPA65R190CFD-ND, Value1="? ohm", Value2="68 nC"
R600: "Varistor 275V RMS 10MM Radial, TH", Manufacturer=TDK, Supplier Part Number 1=495-1433-ND
R601 R602 R603: "RES, 1.65 k, 1%, 0.25 W, 1206", Manufacturer=Vishay-Dale, Power_W=0.25, Supplier Part Number 1=541-1.65KFCT-ND, TempCo="100 ppm/C", Tolerance_%=1, Value1=1%, Value2=0.25W, Value_Code=1k65, ValueDisplayed=1.65k
R604 R633: library part CMP-0079211-1, "ICL 10 OHM 20% 7.5A 21MM", Manufacturer="EPCOS (TDK)", Supplier Part Number 1=495-76297-2-ND, Tolerance_%=±20%
R605 R607: "RES, 10.0, 1%, 0.1 W, 0603", Manufacturer=Vishay-Dale, Power_W=0.1, Supplier Part Number 1=541-10.0HCT-ND, TempCo="100 ppm/C", Tolerance_%=1, Value1=1%, Value2=0.1W, Value_Code=10R0, ValueDisplayed=10.0
R606 R608: "RES, 10 k, 5%, 0.1 W, 0603", Manufacturer="Yageo America", Power_W=0.1, Supplier Part Number 1=311-10KGRCT-ND, TempCo="100 ppm/C", Tolerance_%=5, Value1=5%, Value2=0.1W, Value_Code=10k0, ValueDisplayed=10k
R609: "RES, 36.5 k, 1%, 0.1 W, 0603", Manufacturer=Vishay-Dale, Power_W=0.1, Supplier Part Number 1=541-36.5KHCT-ND, TempCo="100 ppm/C", Tolerance_%=1, Value1=1%, Value2=0.1W, Value_Code=36k5, ValueDisplayed=36.5k
R610: "RES, 10.0 k, 1%, 0.1 W, 0603", Manufacturer=Vishay-Dale, Power_W=0.1, Supplier Part Number 1=541-10.0KHCT-ND, TempCo="100 ppm/C", Tolerance_%=1, Value1=1%, Value2=0.1W, Value_Code=10k0, ValueDisplayed=10.0k
R611: "RES, 150, 1%, 0.25 W, 1206", Manufacturer="Yageo America", Power_W=0.25, Supplier Part Number 1=311-150FRCT-ND, TempCo="100 ppm/C", Tolerance_%=1, Value1=1%, Value2=0.25W, Value_Code=150R, ValueDisplayed=150
R612: "RES, 2.2, 5%, 0.1 W, 0603", Manufacturer=Vishay-Dale, Power_W=0.1, Supplier Part Number 1=541-2.2GCT-ND, TempCo="200 ppm/C", Tolerance_%=5, Value1=5%, Value2=0.1W, Value_Code=2R20, ValueDisplayed=2.2
R613: "RES, 787 k, 1%, 0.1 W, 0603", Manufacturer=Vishay-Dale, Power_W=0.1, Supplier Part Number 1=541-787KHCT-ND, TempCo="100 ppm/C", Tolerance_%=1, Value1=1%, Value2=0.1W, Value_Code=787k
R614: "RES, 300 k, 5%, 0.1 W, 0603", Manufacturer=Vishay-Dale, Power_W=0.1, Supplier Part Number 1=541-300KGCT-ND, TempCo="200 ppm/C", Tolerance_%=5, Value1=5%, Value2=0.1W, Value_Code=300k
R615 R616 R617: "RES, 4.99 M, 1%, 0.25 W, 1206", Manufacturer=Vishay-Dale, Power_W=0.25, Supplier Part Number 1=541-4.99MFCT-ND, TempCo="100 ppm/C", Tolerance_%=1, Value1=1%, Value2=0.25W, Value_Code=4M99, ValueDisplayed=4.99M
R618: "RES, 169 k, 1%, 0.1 W, 0603", Manufacturer="Yageo America", Power_W=0.1, Supplier Part Number 1=311-169KHRCT-ND, TempCo="200 ppm/C", Tolerance_%=1, Value1=1%, Value2=0.1W, Value_Code=169k
R619: "RES, 0, 5%, 0.1 W, 0603", Manufacturer=Vishay-Dale, Power_W=0.1, Supplier Part Number 1=541-0.0GCT-ND, TempCo="200 ppm/C", Tolerance_%=5, Value1=5%, Value2=0.1W, Value_Code=0000, ValueDisplayed=0
R620: "RES, 10 k, 5%, 0.1 W, 0603", Manufacturer=Vishay-Dale, Power_W=0.1, Supplier Part Number 1=541-10KGCT-ND, TempCo="200 ppm/C", Tolerance_%=5, Value1=5%, Value2=0.1W, Value_Code=10k0, ValueDisplayed=10k
R621: "RES, 6.04 k, 1%, 0.1 W, 0603", Manufacturer=Vishay-Dale, Power_W=0.1, Supplier Part Number 1=541-6.04KHCT-ND, TempCo="100 ppm/C", Tolerance_%=1, Value1=1%, Value2=0.1W, Value_Code=6k04, ValueDisplayed=6.04k
R622: "RES, 806 k, 1%, 0.1 W, 0603", Manufacturer=Vishay-Dale, Power_W=0.1, Supplier Part Number 1=541-806KHCT-ND, TempCo="100 ppm/C", Tolerance_%=1, Value1=1%, Value2=0.1W, Value_Code=806k
R624: "RES, 51, 5%, 0.1 W, 0603", Manufacturer=Vishay-Dale, Power_W=0.1, Supplier Part Number 1=541-51GCT-ND, TempCo="200 ppm/C", Tolerance_%=5, Value1=5%, Value2=0.1W, Value_Code=51R0, ValueDisplayed=51
R625: "RES, 255 k, 1%, 0.1 W, 0603", Manufacturer=Vishay-Dale, Power_W=0.1, Supplier Part Number 1=541-255KHCT-ND, TempCo="100 ppm/C", Tolerance_%=1, Value1=1%, Value2=0.1W, Value_Code=255k
R626: "RES, 7.5 k, 5%, 0.1 W, 0603", Manufacturer=Vishay-Dale, Power_W=0.1, Supplier Part Number 1=541-7.5KGCT-ND, TempCo="200 ppm/C", Tolerance_%=5, Value1=5%, Value2=0.1W, Value_Code=7k50, ValueDisplayed=7.5k
R627: "RES, 27 k, 5%, 0.1 W, 0603", Manufacturer=Vishay-Dale, Power_W=0.1, Supplier Part Number 1=541-27KGCT-ND, TempCo="200 ppm/C", Tolerance_%=5, Value1=5%, Value2=0.1W, Value_Code=27k0, ValueDisplayed=27k
R628: "RES, 100, 5%, 0.1 W, 0603", Manufacturer=Vishay-Dale, Power_W=0.1, Supplier Part Number 1=541-100GCT-ND, TempCo="200 ppm/C", Tolerance_%=5, Value1=5%, Value2=0.1W, Value_Code=100R, ValueDisplayed=100
R629 R630 R631 R632: "RES, 1.0 M, 5%, 0.25 W, 1206", Manufacturer=Vishay-Dale, Power_W=0.25, Supplier Part Number 1=541-1.0MECT-ND, TempCo="200 ppm/C", Tolerance_%=5, Value1=5%, Value2=0.25W, Value_Code=1M00, ValueDisplayed=1.0M
S600: library part CMP-0079208-1, "Switch, Slide, DPDT, On-On, 10 A, 125 VAC, 30 VDC, TH", CurrentRating_mA=10kA, Manufacturer="C&K Components", Supplier Part Number 1=CKC3001-ND
T600: library part EE44, "Transformer, 16-pin, TH, Vertical", Alternate Manufacturer=-
U600: library part CMP-0077205-3, "LLC Resonant Controller With High Voltage Start Up Enabling Low Standby Power, DDB0014A (SOIC-14)", Alternate Manufacturer="Texas Instruments", Alternate PartNumber=UCC25630-2DDBT, Operating Temperature Range="-40 to 125 C", Rating=Catalog
U601: "Optocoupler, 5.3 kV, 50-600% CTR, TH", Manufacturer=Vishay-Semiconductor, Supplier Part Number 1=VO618A-ND, Voltage_Isolation_Vrms=5300V
U602: "Adjustable Precision Shunt Regulator, 34 ppm / degC, 100 mA, -40 to 85 degC, 3-pin SOT-23 (DBZ), Green (RoHS & no Sb/Br)", Alternate Manufacturer="Texas Instruments", Alternate PartNumber=Equivalent, Rating=Catalog, Supplier Part Number 1=296-17329-2-ND, Temp Coeff(Max)(ppm/ degree C)=92, Temp Coeff(Typ)(ppm/ degree C)=34
XF1 XF2: "FUSE CLIP CART 250V 6.3A, Single End", Manufacturer=Schurter, Supplier Part Number 1=486-1173-ND

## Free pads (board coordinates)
  round 2.667 hole 1.778: 1(25.08,14) 2(32.08,14) 3(18.08,14)
  oval 1x10 hole 1 slot 10 at 90 deg unplated mask+0.127: 1(50.8,8.636)
  oval 5.08x1 hole 1 slot 5.08 at 0 deg unplated mask+0.127: 1(131.126,80.412) 2(140.843,80.391)

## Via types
v1: diameter 1.27, hole 0.711, Top Layer to Bottom Layer, 55 vias
v2: diameter 0.864, hole 0.406, Top Layer to Bottom Layer, 29 vias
